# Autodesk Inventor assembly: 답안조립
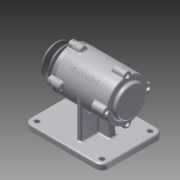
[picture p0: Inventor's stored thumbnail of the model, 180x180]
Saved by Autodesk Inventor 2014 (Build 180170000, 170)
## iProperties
Created: 2015-12
Part Number: 답안조립
Document SubType Name: Assembly
Designer: aapexcom
Author: aapexcom
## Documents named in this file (11)
- C:\Users\aapexcom\Desktop\451208V1006\답안조립.iam
- C:\Users\aapexcom\Desktop\451208V1006\V-벨트풀리.ipt
- C:\Users\aapexcom\Desktop\451208V1006\너트 M12x1.25.ipt
- C:\Users\aapexcom\Desktop\451208V1006\베어링 6204.ipt
- C:\Users\aapexcom\Desktop\451208V1006\본체.ipt
- C:\Users\aapexcom\Desktop\451208V1006\볼트 M4 x 12.ipt
- C:\Users\aapexcom\Desktop\451208V1006\오일실.ipt
- C:\Users\aapexcom\Desktop\451208V1006\축.ipt
- C:\Users\aapexcom\Desktop\451208V1006\커버.ipt
- C:\Users\aapexcom\Desktop\451208V1006\커버2.ipt
- C:\Users\aapexcom\Desktop\451208V1006\키(4 x 4 x 12).ipt
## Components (6 placed, 5 different names)
1. V-벨트풀리:1
2. KS B 1012 클래스 1 일반 - 미터 M12x1.25:1
3. KS B 2023 6204 - 20 x 47 x 14:1
4. KS B 2804 D D - 20 32 8:1
5. KS B 1311 (I) 4 x 4 x 12:1
6. KS B 2023 6204 - 20 x 47 x 14:2
